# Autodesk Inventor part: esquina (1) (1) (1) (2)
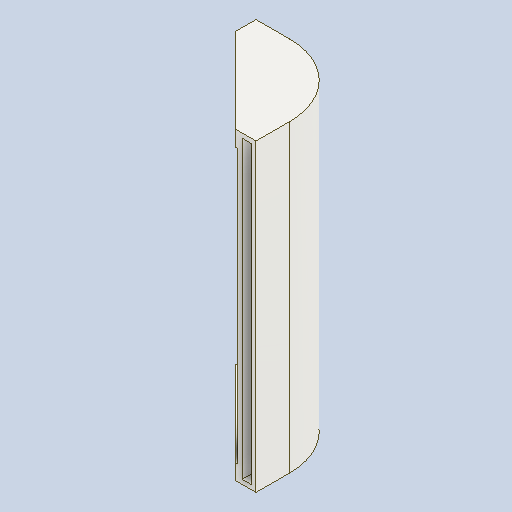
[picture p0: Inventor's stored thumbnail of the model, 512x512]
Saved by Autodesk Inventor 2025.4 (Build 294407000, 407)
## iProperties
Created: 2026-06
Part Number: esquina (1) (1) (1) (2)
Material: Generic
Document SubType Name: Modeling
Designer: AdminForWorker
Density: 1 g/cm^3
Appearance: Default
Title: esquina (1) (1) (1) (2)
Author: AdminForWorker
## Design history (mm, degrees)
feature "esquina (1) (1) (1) (2)"
body "Solid1"
